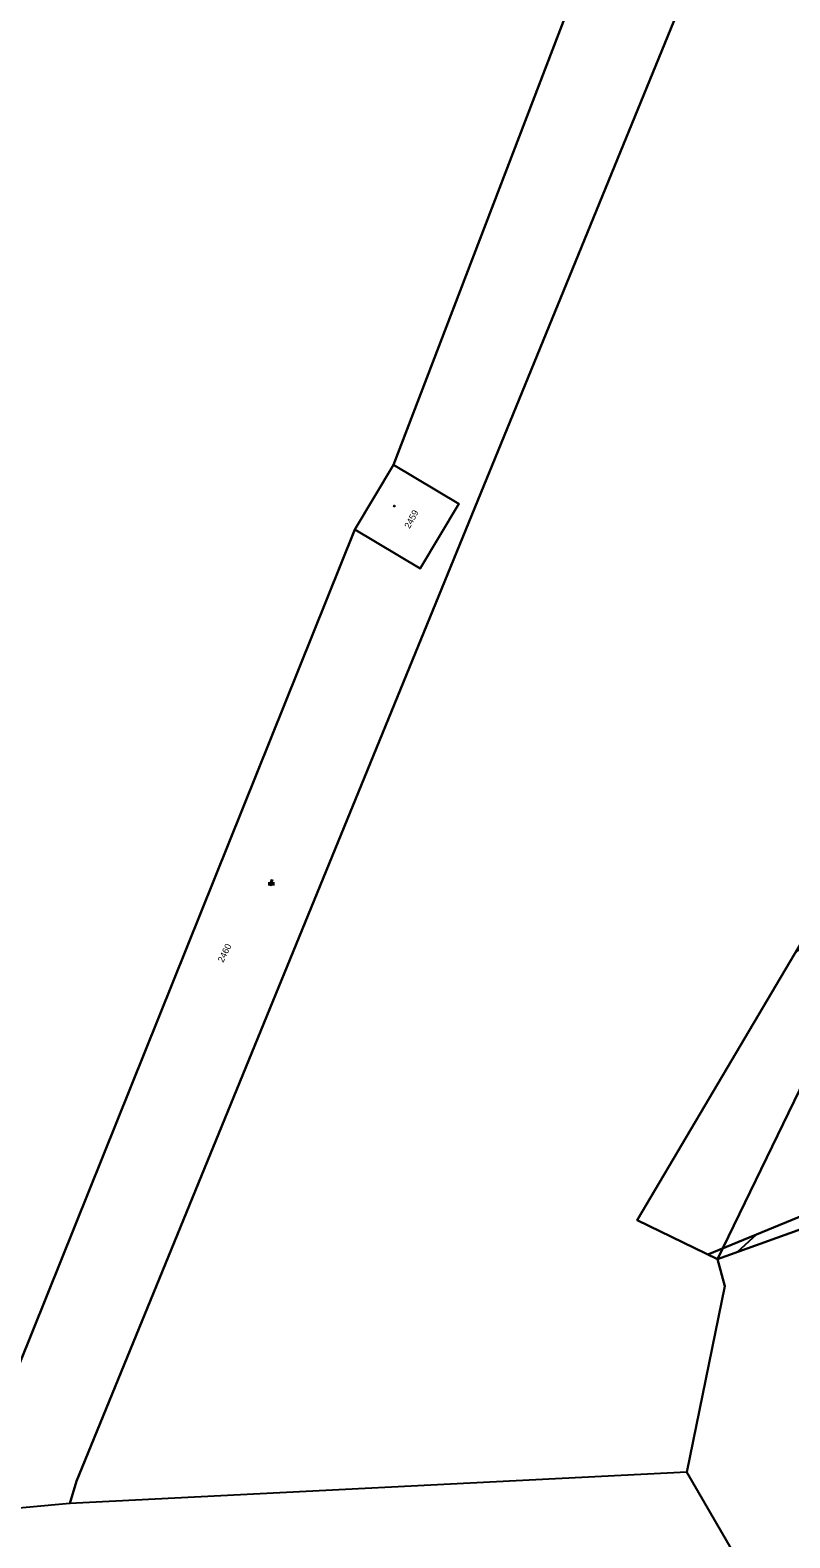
# Model space of a CAD drawing. Extents: x -439750 to -439180, y -1258684 to -1258308.
# Drawn here: x -439433.6 to -439386.7, y -1258628.9 to -1258535.8 of the extents above; entities that cross this region are included whole.
import ezdxf

# ---------------------------------------------------------------- set-up
doc = ezdxf.new("R2010")
doc.units = 0
for name, color, linetype in [('KATASTER', 7, 'Continuous'), ('TARCHY', 7, 'Continuous'), ('UOV', 7, 'Continuous')]:
    doc.layers.add(name, color=color, linetype=linetype)

# ---------------------------------------------------------------- blocks, each defined once
blk = doc.blocks.new('CESTA')
for p, q in [((-0.32, 0.8), (-1, 0.8)), ((-1, 0.4), (-0.46, 0.4)), ((0.1, 2), (-0.6, 0)), ((-0.1, 0), (0.5, 2)), ((0.02, 0.4), (1, 0.4)), ((1, 0.8), (0.14, 0.8))]:
    blk.add_line(p, q)
blk = doc.blocks.new('402')
blk.add_lwpolyline([(0.09, 0.15), (0.18, 0), (0.09, -0.15), (-0.09, -0.15), (-0.18, 0), (-0.09, 0.15), (0.09, 0.15)])

msp = doc.modelspace()

# ---------------------------------------------------------------- linework, layer by layer
at = {"layer": 'KATASTER'}
for points in [[(-439548.5, -1258497.7), (-439538.17, -1258484.88), (-439520.19, -1258486.95), (-439507.21, -1258497.49), (-439484.47, -1258496.42), (-439400.54, -1258499.28), (-439387.09, -1258499.74), (-439411.19, -1258562.66), (-439413.56, -1258566.65), (-439437.77, -1258626.82), (-439438.12, -1258627.38), (-439482.75, -1258611.76), (-439518.67, -1258591.95), (-439550.54, -1258581.84), (-439567.51, -1258574.36), (-439597.45, -1258561.13)], [(-439293.6, -1258595.16), (-439302.92, -1258592.03), (-439309.07, -1258589.96), (-439321.61, -1258588.07), (-439333.61, -1258586.25), (-439352.45, -1258575.82), (-439372.84, -1258577.9), (-439376.35, -1258581.07), (-439391.21, -1258611.67), (-439396.15, -1258609.27), (-439374.58, -1258572.75), (-439350.12, -1258570.77), (-439327.4, -1258582.06), (-439308.16, -1258585.09), (-439288.16, -1258587.94)]]:
    msp.add_lwpolyline(points, dxfattribs=at)
for points in [[(-439387.09, -1258499.74), (-439378.69, -1258503.81), (-439384.01, -1258511.1), (-439430.73, -1258625.37), (-439431.15, -1258626.74), (-439438.12, -1258627.38), (-439437.77, -1258626.82), (-439413.56, -1258566.65), (-439409.53, -1258569.06), (-439407.15, -1258565.07), (-439411.19, -1258562.66)], [(-439378.69, -1258503.81), (-439348.78, -1258505.65), (-439344.2, -1258505.65), (-439347.2, -1258516.43), (-439357.91, -1258554.88), (-439352.98, -1258561.5), (-439344.31, -1258566.93), (-439324.86, -1258574.68), (-439327.4, -1258582.06), (-439350.12, -1258570.77), (-439374.58, -1258572.75), (-439396.15, -1258609.27), (-439391.21, -1258611.67), (-439390.74, -1258613.33), (-439393.1, -1258624.81), (-439431.15, -1258626.74), (-439430.73, -1258625.37), (-439384.01, -1258511.1)], [(-439411.19, -1258562.66), (-439407.15, -1258565.07), (-439409.53, -1258569.06), (-439413.56, -1258566.65)], [(-439391.21, -1258611.67), (-439376.35, -1258581.07), (-439372.84, -1258577.9), (-439352.45, -1258575.82), (-439333.61, -1258586.25), (-439340.29, -1258591.37), (-439345.17, -1258595.12), (-439346.71, -1258595.67)], [(-439391.21, -1258611.67), (-439346.71, -1258595.67), (-439348.19, -1258596.88), (-439371.96, -1258607.01), (-439312.54, -1258618.96), (-439310.57, -1258605.65), (-439310.21, -1258605.7), (-439307.77, -1258606.04), (-439307.57, -1258608.58), (-439310.7, -1258622.02), (-439332.77, -1258618.14), (-439337.57, -1258641.06), (-439389.53, -1258630.94), (-439393.1, -1258624.81), (-439390.74, -1258613.33)]]:
    msp.add_lwpolyline(points, close=True, dxfattribs=at)
at = {"layer": 'TARCHY'}
msp.add_lwpolyline([(-439389.98, -1258611.23), (-439391.21, -1258611.67), (-439391.8, -1258611.38), (-439388.79, -1258610.14)], close=True, dxfattribs=at)
at = {"layer": 'UOV'}
for points in [[(-439386.39, -1258592.75), (-439375.58, -1258584.59), (-439370.2, -1258572.4), (-439358.37, -1258571.44), (-439355.2, -1258571.18), (-439344.89, -1258580.71), (-439340.65, -1258585.86), (-439350.39, -1258594.35), (-439391.8, -1258611.38), (-439396.15, -1258609.27)], [(-439345.17, -1258595.12), (-439346.71, -1258595.67), (-439391.21, -1258611.67), (-439391.8, -1258611.38), (-439350.39, -1258594.35), (-439340.65, -1258585.86), (-439335.71, -1258587.86), (-439338.24, -1258589.8), (-439340.29, -1258591.37)]]:
    msp.add_lwpolyline(points, close=True, dxfattribs=at)

# ---------------------------------------------------------------- block references
at = {"layer": 'KATASTER', "xscale": 0.2, "yscale": 0.20000000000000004}
for name, p in [('402', (-439411.13, -1258565.2)), ('CESTA', (-439418.72, -1258588.64))]:
    msp.add_blockref(name, p, dxfattribs=at)

# ---------------------------------------------------------------- texts
at = {"layer": 'KATASTER'}
for s, rotation, p in [('2459', 61.364, (-439410.19, -1258566.632)), ('2460', 63.77, (-439421.688, -1258593.4))]:
    msp.add_text(s, height=0.4, rotation=rotation, dxfattribs=at).set_placement(p)

doc.saveas('drawing.dxf')
